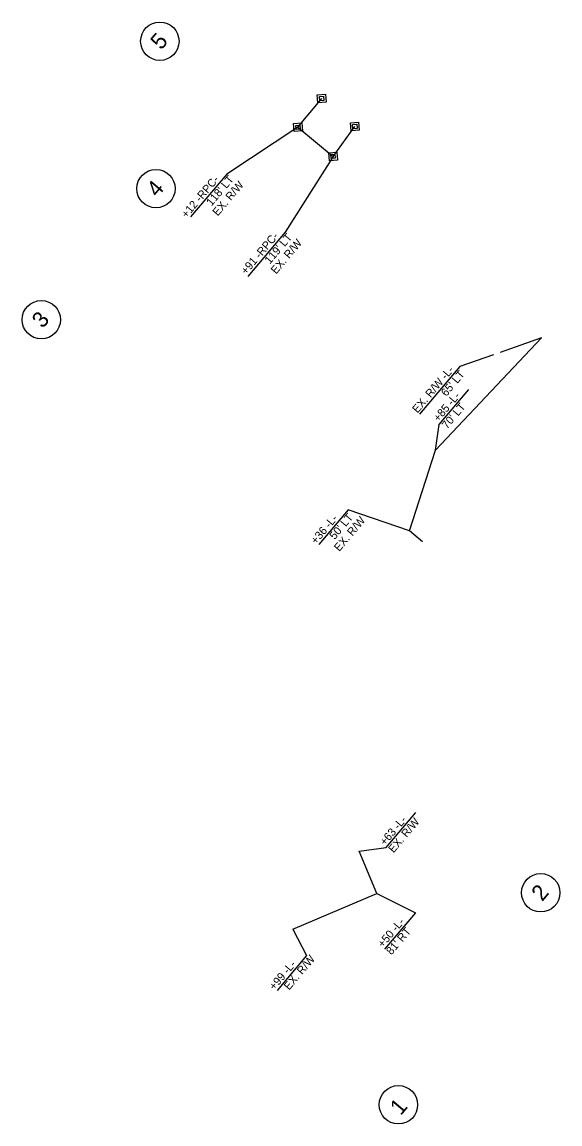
# Model space of a CAD drawing. Extents: x 1761749 to 1764136, y 422439 to 425054.
# Drawn here: x 1761749 to 1762085, y 422439 to 423128 of the extents above; entities that cross this region are included whole.
import ezdxf

# ---------------------------------------------------------------- set-up
doc = ezdxf.new("R2010")
doc.units = 0
for name, color, linetype in [('Prop Easement Construction', 7, 'Continuous'), ('Prop Easement Construction Station Offsets', 7, 'Continuous'), ('Prop Easement Permanent Utility', 7, 'Continuous'), ('Prop Easement Permanent Utility Station Offsets', 7, 'Continuous'), ('Prop Parcel Number CELL', 7, 'Continuous'), ('Prop Parcel Number Text', 7, 'Continuous'), ('Prop ROW Permanent Easement CELL', 7, 'Continuous')]:
    doc.layers.add(name, color=color, linetype=linetype)

msp = doc.modelspace()

# ---------------------------------------------------------------- linework, layer by layer
at = {"layer": 'Prop Easement Construction'}
for p, q in [((1761998.79, 422803), (1761990.68, 422809.88)), ((1761970.4, 422583.28), (1761959.41, 422609.63)), ((1761917.8, 422561), (1761970.4, 422583.28))]:
    msp.add_line(p, q, dxfattribs=at)
msp.add_lwpolyline([(1761990.68, 422809.88), (1762007.09, 422860.19), (1762073.19, 422930.48)], dxfattribs=at)
at = {"layer": 'Prop Easement Construction Station Offsets'}
for points in [[(1762073.19, 422930.48), (1762047.31, 422921.37)], [(1762043.24, 422919.93), (1762022.24, 422912.53), (1761997, 422882.74)], [(1762007.09, 422860.19), (1762009.29, 422876.43), (1762027.74, 422898.21)], [(1761990.68, 422809.88), (1761952.52, 422823.06), (1761934.07, 422801.28)], [(1761959.41, 422609.63), (1761976.22, 422612), (1761994.67, 422633.78)], [(1761970.4, 422583.28), (1761994.4, 422571.23), (1761975.09, 422548.43)], [(1761917.8, 422561), (1761926.48, 422544.43), (1761908.04, 422522.65)]]:
    msp.add_lwpolyline(points, dxfattribs=at)
at = {"layer": 'Prop Easement Permanent Utility'}
for p, q in [((1761921.07, 423062.08), (1761935.92, 423080.07)), ((1761921.07, 423062.08), (1761943.03, 423043.83)), ((1761943.03, 423043.83), (1761956.59, 423062.56))]:
    msp.add_line(p, q, dxfattribs=at)
at = {"layer": 'Prop Easement Permanent Utility Station Offsets'}
for points in [[(1761921.07, 423062.08), (1761876.6, 423032.7), (1761854.04, 423006.07)], [(1761943.03, 423043.83), (1761913.03, 422996.42), (1761889.72, 422968.91)]]:
    msp.add_lwpolyline(points, dxfattribs=at)
at = {"layer": 'Prop Parcel Number CELL'}
for p, q in [((1761834.79, 423115.84), (1761834.79, 423115.84)), ((1761832.35, 423023.75), (1761832.35, 423023.75)), ((1761760.72, 422941.82), (1761760.72, 422941.82)), ((1762072.73, 422583.68), (1762072.73, 422583.68)), ((1761983.85, 422451.21), (1761983.85, 422451.21))]:
    msp.add_line(p, q, dxfattribs=at)
for centre in [(1761834.79, 423115.84), (1761832.35, 423023.75), (1761760.72, 422941.82), (1762072.73, 422583.68), (1761983.85, 422451.21)]:
    msp.add_circle(centre, 12, dxfattribs=at)
at = {"layer": 'Prop ROW Permanent Easement CELL'}
for p, q in [((1761935.92, 423080.07), (1761935.92, 423080.07)), ((1761921.07, 423062.08), (1761921.07, 423062.08)), ((1761956.59, 423062.56), (1761956.59, 423062.56)), ((1761943.03, 423043.83), (1761943.03, 423043.83))]:
    msp.add_line(p, q, dxfattribs=at)
for points in [[(1761933.59, 423077.32), (1761933.17, 423082.39), (1761938.25, 423082.81), (1761938.67, 423077.74)], [(1761934.76, 423078.69), (1761934.55, 423081.23), (1761937.08, 423081.44), (1761937.29, 423078.9)], [(1761918.74, 423059.33), (1761918.32, 423064.41), (1761923.4, 423064.83), (1761923.82, 423059.75)], [(1761919.91, 423060.71), (1761919.7, 423063.24), (1761922.23, 423063.45), (1761922.44, 423060.92)], [(1761954.26, 423059.82), (1761953.84, 423064.89), (1761958.92, 423065.31), (1761959.34, 423060.24)], [(1761955.43, 423061.19), (1761955.22, 423063.73), (1761957.75, 423063.94), (1761957.96, 423061.4)], [(1761940.7, 423041.08), (1761940.28, 423046.16), (1761945.36, 423046.58), (1761945.78, 423041.5)], [(1761941.87, 423042.46), (1761941.66, 423044.99), (1761944.19, 423045.2), (1761944.4, 423042.67)]]:
    msp.add_lwpolyline(points, close=True, dxfattribs=at)

# ---------------------------------------------------------------- texts
at = {"layer": 'Prop Easement Construction Station Offsets'}
for s, p in [('EX. R/W -L-', (1761995.76, 422883.1)), ("65' LT", (1762013.75, 422893.51)), ('+85 -L-', (1762008.9, 422877.7)), ("70' LT", (1762014.24, 422873.17)), ('+36 -L-', (1761932.37, 422801.13)), ("50' LT", (1761944.02, 422804.05)), ('EX. R/W', (1761946.9, 422796.62)), ('+63 -L-', (1761975.44, 422612.8)), ('EX. R/W', (1761980.78, 422608.27)), ('+50 -L-', (1761974.14, 422549.04)), ("81' RT", (1761979.48, 422544.52)), ('+99 -L-', (1761906.35, 422522.49)), ('EX. R/W', (1761915.53, 422522.5))]:
    msp.add_text(s, height=5, rotation=49.7301, dxfattribs=at).set_placement(p)
at = {"layer": 'Prop Easement Permanent Utility Station Offsets'}
for s, p in [('+12 -RPC-', (1761851.54, 423004.99)), ("118' LT", (1761867.08, 423012.5)), ('EX. R/W', (1761870.97, 423006.26)), ('+91 -RPC-', (1761888.75, 422969.63)), ("119' LT", (1761903.51, 422976.22)), ('EX. R/W', (1761907.4, 422969.98))]:
    msp.add_text(s, height=5, rotation=49.7301, dxfattribs=at).set_placement(p)
at = {"layer": 'Prop Parcel Number Text'}
for s, p in [('5', (1761835.64, 423109.93)), ('4', (1761833.24, 423017.89)), ('3', (1761761.59, 422935.94)), ('2', (1762073.64, 422577.84)), ('1', (1761985.27, 422444.08))]:
    msp.add_text(s, height=10, rotation=49.7301, dxfattribs=at).set_placement(p)

doc.saveas('drawing.dxf')
